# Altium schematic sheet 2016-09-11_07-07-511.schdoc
size 339 x 185 mm; SheetNumber: 1; SheetTotal: 1
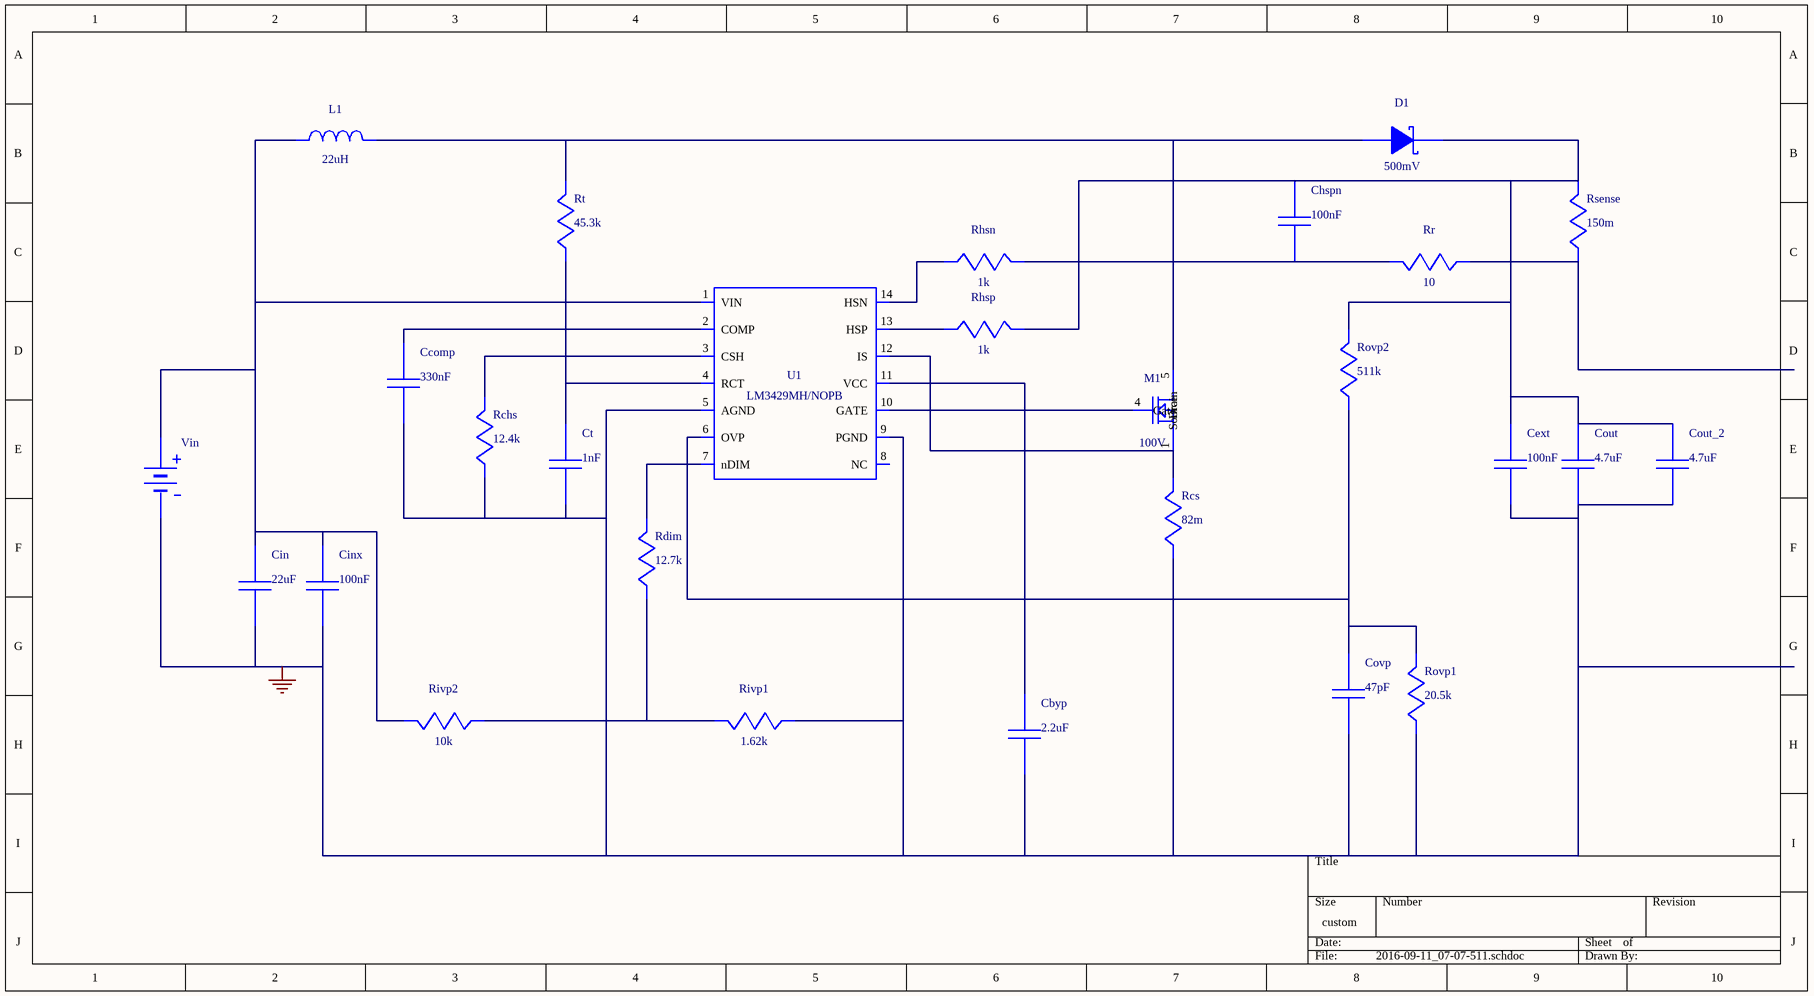
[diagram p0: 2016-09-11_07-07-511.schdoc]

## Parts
Cbyp  value 2.2uF  (hidden comment: EMK212B7225KG-T)
Ccomp  value 330nF  (hidden comment: GRM155R60J334KE01D)
Cext  value 100nF  (hidden comment: C0805C104K5RACTU)
Chspn  value 100nF  (hidden comment: GRM21BR71E104KA01L)
Cin  value 22uF  (hidden comment: GRM32ER61E226KE15L)
Cinx  value 100nF  (hidden comment: C0603C104K5RACTU)
Cout  value 4.7uF  (hidden comment: GRM31CR71H475KA12L)
Cout_2  value 4.7uF  (hidden comment: GRM31CR71H475KA12L)
Covp  value 47pF  (hidden comment: C0805C470K5GACTU)
Ct  value 1nF  (hidden comment: CL21C102JBCNFNC)
D1  value 500mV  (hidden comment: B340A-13-F)
L1  value 22uH  (hidden comment: SDR1105-220ML)
M1  value 100V  (hidden comment: CSD19537Q3)
Rchs  value 12.4k  (hidden comment: CRCW040212K4FKED)
Rcs  value 82m  (hidden comment: CRM2010-FZ-R082ELF)
Rdim  value 12.7k  (hidden comment: CRCW040212K7FKED)
Rhsn  value 1k  (hidden comment: CRCW04021K00FKED)
Rhsp  value 1k  (hidden comment: CRCW04021K00FKED)
Rivp1  value 1.62k  (hidden comment: CRCW04021K62FKED)
Rivp2  value 10k  (hidden comment: CRCW040210K0FKED)
Rovp1  value 20.5k  (hidden comment: CRCW040220K5FKED)
Rovp2  value 511k  (hidden comment: CRCW0402511KFKED)
Rr  value 10  (hidden comment: CRCW040210R0FKED)
Rsense  value 150m  (hidden comment: ERJ-3RSFR15V)
Rt  value 45.3k  (hidden comment: CRCW040245K3FKED)
U1  LM3429MH  (value not drawn)
Vin  WB_BATTERY  (value not drawn)

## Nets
0: Cbyp.2 Ccomp.2 Cext.2 Cin.2 Cinx.2 Cout.2 Cout_2.2 Covp.2 Ct.2 Rchs.2 Rcs.2 Rivp1.2 Rovp1.2 U1.5(AGND) U1.9(PGND) U1.15(DAP) Vin.2(-)
NetCbyp_1: Cbyp.1 U1.11(VCC)
NetCcomp_1: Ccomp.1 U1.2(COMP)
NetCext_1: Cext.1 Chspn.1 Cout.1 Cout_2.1 D1.1(K) Rhsp.1 Rovp2.1 Rsense.1
NetChspn_2: Chspn.2 Rhsn.1 Rr.1
NetCin_1: Cin.1 Cinx.1 L1.1 Rivp2.1 U1.1(VIN) Vin.1(+)
NetCovp_1: Covp.1 Rovp1.1 Rovp2.2 U1.6(OVP)
NetCt_1: Ct.1 Rt.2 U1.4(RCT)
NetD1_2: D1.2(A) L1.2 M1.5(Drain) M1.6(Drain) M1.7(Drain) M1.8(Drain) M1.9(Drain) Rt.1
NetM1_1: M1.1(Source) M1.2(Source) M1.3(Source) Rcs.1 U1.12(IS)
NetM1_4: M1.4(Gate) U1.10(GATE)
NetRchs_1: Rchs.1 U1.3(CSH)
NetRdim_1: Rdim.1 U1.7(nDIM)
NetRdim_2: Rdim.2 Rivp1.1 Rivp2.2
NetRhsn_2: Rhsn.2 U1.14(HSN)
NetRhsp_2: Rhsp.2 U1.13(HSP)
NetRr_2: Rr.2 Rsense.2

Not connected (* = marked no-connect by the designer): U1 8(NC)

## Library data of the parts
Cbyp = EMK212B7225KG-T: Manufacturer Name: Taiyo Yuden
Ccomp = GRM155R60J334KE01D: GRM155R60J334KE0; Manufacturer Name: MuRata
Cext = C0805C104K5RACTU: Manufacturer Name: Kemet
Chspn = GRM21BR71E104KA01L: GRM21BR71E104KA0; Manufacturer Name: MuRata
Cin = GRM32ER61E226KE15L: GRM32ER61E226KE1; Manufacturer Name: MuRata
Cinx = C0603C104K5RACTU: Manufacturer Name: Kemet
Cout Cout_2 = GRM31CR71H475KA12L: GRM31CR71H475KA1; Manufacturer Name: MuRata
Covp = C0805C470K5GACTU: Manufacturer Name: Kemet
Ct = CL21C102JBCNFNC: Manufacturer Name: Samsung Electro-Mechanics
D1 = B340A-13-F: Manufacturer Name: Diodes Inc.
L1 = SDR1105-220ML: Manufacturer Name: Bourns
M1 = CSD19537Q3: Manufacturer Name: Texas Instruments
Rchs = CRCW040212K4FKED: Manufacturer Name: Vishay-Dale
Rcs = CRM2010-FZ-R082ELF: CRM2010-FZ-R082E; Manufacturer Name: Bourns
Rdim = CRCW040212K7FKED: Manufacturer Name: Vishay-Dale
Rhsn Rhsp = CRCW04021K00FKED: Manufacturer Name: Vishay-Dale
Rivp1 = CRCW04021K62FKED: Manufacturer Name: Vishay-Dale
Rivp2 = CRCW040210K0FKED: Manufacturer Name: Vishay-Dale
Rovp1 = CRCW040220K5FKED: Manufacturer Name: Vishay-Dale
Rovp2 = CRCW0402511KFKED: Manufacturer Name: Vishay-Dale
Rr = CRCW040210R0FKED: Manufacturer Name: Vishay-Dale
Rsense = ERJ-3RSFR15V: Manufacturer Name: Panasonic
Rt = CRCW040245K3FKED: Manufacturer Name: Vishay-Dale
U1 = LM3429MH: LM3429MH/NOPB; Manufacturer Name: Texas Instruments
